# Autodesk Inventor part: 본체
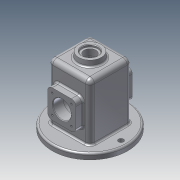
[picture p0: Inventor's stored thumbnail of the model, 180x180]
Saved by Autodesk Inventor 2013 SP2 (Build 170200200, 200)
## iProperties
Created: 2021-08
Part Number: 본체
Material: 알루미늄 6061
Document SubType Name: Modeling
Designer: kum60
Density: 2.71 g/cm^3
Mass: 819.632 g
Surface Area: 945.583 cm^2
Volume: 302.447 cm^3
Author: kum60
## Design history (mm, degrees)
sketch "스케치1"
  geometry: L1 (37, 37)-(-37, 37); L2 (-37, 37)-(-37, -37); L3 (-37, -37)-(37, -37); L4 (37, -37)-(37, 37); L5 (37, 37)-(-37, -37); L6 (-37, 37)-(37, -37); 1 further point
  constraints: 12 end point, 2 midpoint, 2 parallel, 1 horizontal, 1 perpendicular
  dimensions: "d0" = 74 distance of L3.end L2.end; "d1" = 74 distance of L2.end L1.end
extrude "돌출1" new body sketch "스케치1" stored distance "d2" = 100; taper "d3" = 0 deg
feature "쉘1" dims "d4" = 5
sketch "스케치2"
  geometry: L1 (74, -100)-(0, -100) reference; L2 (37, -50)-(37, -55); C1 r 16 at (37, -55); 1 further point
  constraints: 2 coincident, 2 end point, 1 centre point, 1 perpendicular
  dimensions: "d91" = 5 distance of L2.start L2.end; "d92" = 32 diameter of C1
extrude "돌출2" cut sketch "스케치2" stored distance "d6" = 0; taper "d7" = 0 deg
sketch "스케치15"
  geometry: L1 (12, -80)-(62, -80); L2 (62, -80)-(62, -30); L3 (62, -30)-(12, -30); L4 (12, -30)-(12, -80); L5 (12, -80)-(62, -30); L6 (62, -80)-(12, -30); C1 r 16 at (37, -55) reference; 1 further point
  constraints: 12 end point, 2 midpoint, 2 parallel, 1 horizontal, 1 perpendicular
  dimensions: "d93" = 50 distance of L3.end L2.end; "d94" = 50 distance of L2.end L1.end
extrude "돌출9" join sketch "스케치15" distance "d95" = 13; taper "d96" = 0 deg
sketch "스케치16"
  geometry: C1 r 16 at (32, 45) reference; C2 r 25 at (32, 45); 1 further point
  constraints: 1 centre point, 1 coincident
  dimensions: "d97" = 50 diameter of C2
extrude "돌출10" join sketch "스케치16" distance "d98" = 7; taper "d99" = -10 deg
sketch "스케치17"
  geometry: L1 (20, -72)-(54, -72); L2 (54, -72)-(54, -38); L3 (54, -38)-(20, -38); L4 (20, -38)-(20, -72); L5 (20, -72)-(54, -38); L6 (54, -72)-(20, -38); C1 r 16 at (37, -55) reference; 5 further points
  constraints: 12 end point, 3 coincident, 2 midpoint, 2 parallel, 1 horizontal, 1 perpendicular, 1 point on line
  dimensions: "d100" = 34 distance of L3.end L2.end; "d101" = 34 distance of L2.end L1.end
hole "구멍5" sketch "스케치17" at (20, -38), (54, -38), (54, -72), (20, -72) diameter "d102" = 3.242; stored, may be unused: countersink angle "d106" = 90 deg, drill point angle "d108" = 118 deg; dims "d103" = 8, "d104" = 28, "d105" = 4, "d107" = 10
sketch "스케치6"
  geometry: C1 r 25 at (0, 0); 1 further point
  constraints: 1 centre point, 1 coincident
  dimensions: "d34" = 50 diameter of C1
extrude "돌출5" join sketch "스케치6" distance "d35" = 10; taper "d36" = -6 deg
sketch "스케치13"
  geometry: C1 r 23.949 at (0, 0) reference; C2 r 20 at (0, 0); C3 r 30 at (0, 0)
  constraints: 2 centre point, 2 coincident
  dimensions: "d79" = 40 diameter of C2; "d80" = 60 diameter of C3
extrude "돌출8" cut sketch "스케치13" distance "d81" = 10; taper "d82" = -6 deg
sketch "스케치7"
  geometry: C1 r 23.949 at (0, 0) reference; 1 further point
  constraints: 1 coincident
hole "구멍2" sketch "스케치7" at (0, 0) diameter "d37" = 21; stored, may be unused: countersink angle "d41" = 90 deg, drill point angle "d43" = 118 deg; dims "d38" = 8, "d39" = 28, "d40" = 4, "d42" = 10
sketch "스케치10"
  geometry: L1 (32, 32)-(32, -32) reference; L2 (32, -32)-(-32, -32) reference; L3 (-32, -32)-(-32, 32) reference; L4 (-32, 32)-(32, 32) reference; C1 r 67 at (0, 0); 1 further point
  constraints: 1 centre point, 1 coincident
  dimensions: "d60" = 134 diameter of C1
extrude "돌출7" join sketch "스케치10" distance "d61" = 10; taper "d62" = 0 deg
fillet "모깎기7" dims "d63" = 3
fillet "모깎기8" dims "d64" = 3
fillet "모깎기5" dims "d58" = 8
sketch "스케치11"
  geometry: L1 (37, 29)-(37, -29) reference; L2 (55, 0)-(-55, 0); C1 r 64 at (0, 0) reference; 3 further points
  constraints: 3 coincident, 2 end point, 1 midpoint, 1 perpendicular
  dimensions: "d65" = 110 distance of L2.start L2.end
hole "구멍4" sketch "스케치11" at (55, 0), (-55, 0) diameter "d66" = 9; stored, may be unused: countersink angle "d70" = 90 deg, drill point angle "d72" = 118 deg; dims "d67" = 8, "d68" = 28, "d69" = 4, "d71" = 10
fillet "모깎기9" dims "d73" = 3
chamfer "모따기3" distance "d44" = 1; stored, may be unused: second distance "d45" = 2, angle "d46" = 45 deg
fillet "모깎기10" dims "d83" = 3
fillet "모깎기11" dims "d84" = 8
sketch "스케치14"
  geometry: L1 (49, 107)-(9, 107) reference; L2 (-8, 89)-(-8, 0) reference; 2 further points
  constraints: 1 other
  dimensions: "d85" = 28 distance from line of point (29, 79) L1; "d86" = 37 distance from line of point (29, 79) L2
feature "엠보싱2" sketch "스케치14" dims "d0" = 74, "d1" = 74, "d87" = 0.5, "d88" = 0
fillet "모깎기12" dims "d109" = 8
fillet "모깎기13" dims "d110" = 3
chamfer "모따기4" distance "d111" = 1; stored, may be unused: second distance "d112" = 2, angle "d113" = 45 deg
node "솔리드1"
mirror "대칭2"
